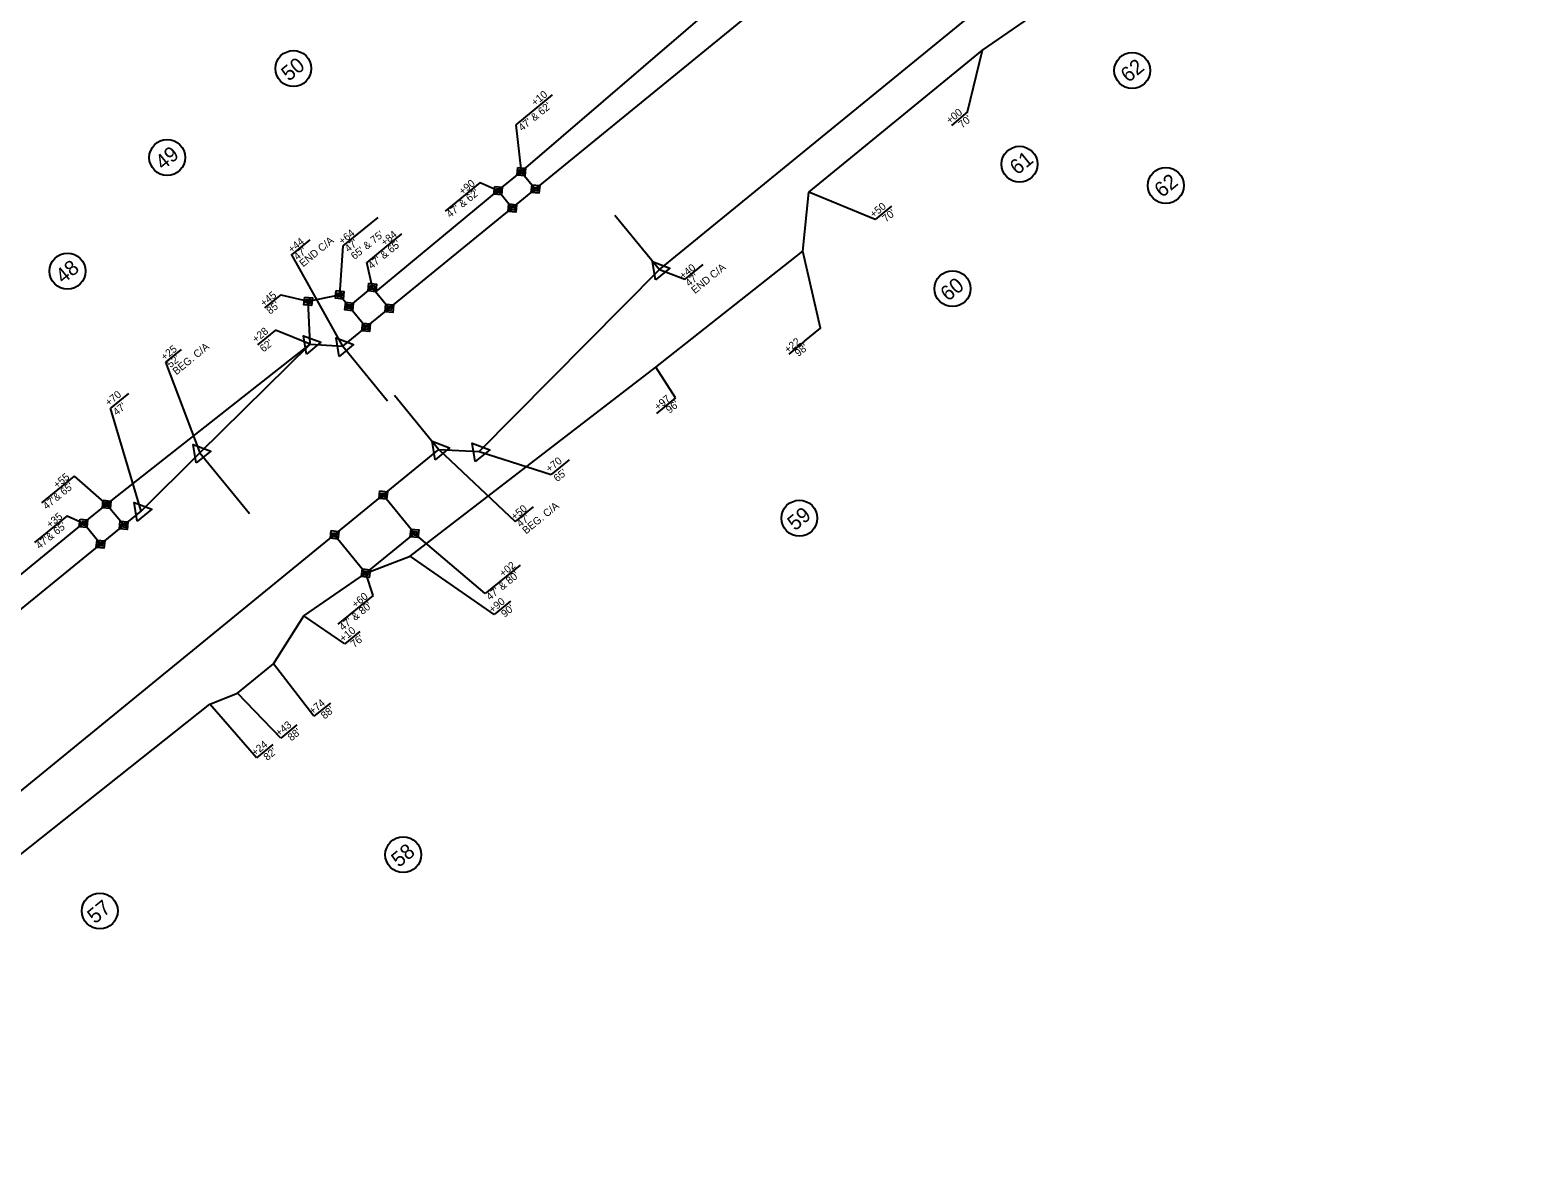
# Model space of a CAD drawing. Extents: x 2320946 to 2332748, y 597838 to 612698.
# Drawn here: x 2323947 to 2324954, y 599553 to 600307 of the extents above; entities that cross this region are included whole.
import ezdxf

# ---------------------------------------------------------------- set-up
doc = ezdxf.new("R2010")
doc.units = 0
for name, color, linetype in [('Prop Easement Construction', 7, 'Continuous'), ('Prop Easement Construction Station Offsets', 7, 'Continuous'), ('Prop Easement Permanent Drainage', 7, 'Continuous'), ('Prop Easement Permanent Drainage Station Offsets', 7, 'Continuous'), ('Prop Easement Permanent Drainage Utility', 7, 'Continuous'), ('Prop Easement Permanent Utility', 7, 'Continuous'), ('Prop Easement Permanent Utility Station Offsets', 7, 'Continuous'), ('Prop Parcel Number CELL', 7, 'Continuous'), ('Prop ROW CA Lines', 7, 'Continuous'), ('Prop ROW Marker CELL', 7, 'Continuous'), ('Prop ROW Permanent Easement CELL', 7, 'Continuous'), ('Prop ROW RW CA Lines', 7, 'Continuous'), ('Prop ROW RW Lines', 7, 'Continuous'), ('Prop ROW Station Offsets', 7, 'Continuous')]:
    doc.layers.add(name, color=color, linetype=linetype)

msp = doc.modelspace()

# ---------------------------------------------------------------- linework, layer by layer
at = {"layer": 'Prop Easement Construction'}
for p, q in [((2324275, 600212.5), (2324665.7, 600548.3)), ((2324583.1, 600293.7), (2324953.9, 600551.1)), ((2324467, 600198.8), (2324583.1, 600293.7)), ((2324177.8, 600132.4), (2324259.5, 600199.9)), ((2324463, 600159.4), (2324467, 600198.8)), ((2324364.9, 600081.9), (2324463, 600159.4)), ((2323998.1, 599990.3), (2324134, 600097.4)), ((2324200.7, 599955.7), (2324364.9, 600081.9)), ((2323839.3, 599860.7), (2323982.6, 599977.7)), ((2324171.2, 599944.4), (2324200.7, 599955.7)), ((2324129.9, 599915.9), (2324171.2, 599944.4)), ((2324109.6, 599883.8), (2324129.9, 599915.9)), ((2324085.6, 599864.2), (2324109.6, 599883.8)), ((2324067.1, 599856.9), (2324085.6, 599864.2)), ((2323904.1, 599727.7), (2324067.1, 599856.9))]:
    msp.add_line(p, q, dxfattribs=at)
at = {"layer": 'Prop Easement Construction Station Offsets'}
for p, q in [((2324573.1, 600252.4), (2324562.2, 600243.4)), ((2324522.3, 600189.6), (2324511.3, 600180.6)), ((2324464.2, 600099.3), (2324453.6, 600090.6)), ((2324378.1, 600061.5), (2324365.3, 600051)), ((2324267.7, 599925.7), (2324256.8, 599916.8)), ((2324167.2, 599905.5), (2324157.1, 599897.3)), ((2324147.5, 599857.7), (2324136.5, 599848.8)), ((2324125.2, 599843.1), (2324114.4, 599834.3)), ((2324109.1, 599830), (2324098.2, 599821.1))]:
    msp.add_line(p, q, dxfattribs=at)
for points in [[(2324573.1, 600252.4), (2324583.1, 600293.7)], [(2324511.3, 600180.6), (2324467, 600198.8)], [(2324464.2, 600099.3), (2324474.8, 600108), (2324463, 600159.4)], [(2324378.1, 600061.5), (2324364.9, 600081.9)], [(2324256.8, 599916.8), (2324200.7, 599955.7)], [(2324157.1, 599897.3), (2324129.9, 599915.9)], [(2324136.5, 599848.8), (2324109.6, 599883.8)], [(2324114.4, 599834.3), (2324085.6, 599864.2)], [(2324098.2, 599821.1), (2324067.1, 599856.9)]]:
    msp.add_lwpolyline(points, dxfattribs=at)
at = {"layer": 'Prop Easement Permanent Drainage'}
for p, q in [((2324259.5, 600199.9), (2324275, 600212.5)), ((2324275, 600212.5), (2324284.5, 600200.9)), ((2324259.5, 600199.9), (2324269, 600188.3)), ((2324160, 600122.5), (2324175.5, 600135.2)), ((2324175.5, 600135.2), (2324186.9, 600121.2)), ((2323982.6, 599977.7), (2323998.1, 599990.3)), ((2324009.5, 599976.4), (2323998.1, 599990.3))]:
    msp.add_line(p, q, dxfattribs=at)
at = {"layer": 'Prop Easement Permanent Drainage Station Offsets'}
for p, q in [((2324295.7, 600263.9), (2324271.3, 600243.9)), ((2324271.3, 600243.9), (2324275, 600212.5)), ((2324247.5, 600205.2), (2324224.2, 600186.2)), ((2324195.1, 600171), (2324171.8, 600151.9)), ((2323976.5, 600009.1), (2323954.7, 599991.3)), ((2323971.8, 599982.7), (2323950, 599964.9)), ((2323994, 599963.8), (2323982.6, 599977.7))]:
    msp.add_line(p, q, dxfattribs=at)
for points in [[(2324247.5, 600205.2), (2324259.5, 600199.9)], [(2324171.7, 600152), (2324175.5, 600135.2)], [(2323976.5, 600009.1), (2323998.1, 599990.3)], [(2323971.8, 599982.7), (2323982.6, 599977.7)]]:
    msp.add_lwpolyline(points, dxfattribs=at)
at = {"layer": 'Prop Easement Permanent Drainage Utility'}
msp.add_line((2324160, 600122.5), (2324171.4, 600108.6), dxfattribs=at)
at = {"layer": 'Prop Easement Permanent Utility'}
for p, q in [((2324132.7, 600126), (2324153.7, 600130.3)), ((2324134, 600097.4), (2324132.7, 600126)), ((2324153.7, 600130.3), (2324160, 600122.5)), ((2324203.7, 599971), (2324182.8, 599996.6)), ((2324150.3, 599970), (2324171.2, 599944.4)), ((2324171.2, 599944.4), (2324203.7, 599971))]:
    msp.add_line(p, q, dxfattribs=at)
at = {"layer": 'Prop Easement Permanent Utility Station Offsets'}
for p, q in [((2324179.3, 600182), (2324155.9, 600163)), ((2324114.5, 600130.4), (2324103.6, 600121.5)), ((2324251, 599930.9), (2324203.7, 599971)), ((2324274.2, 599949.8), (2324251, 599930.9)), ((2324176, 599929.4), (2324152.6, 599910.4))]:
    msp.add_line(p, q, dxfattribs=at)
for points in [[(2324155.9, 600163), (2324153.7, 600130.3)], [(2324114.5, 600130.4), (2324132.7, 600126)], [(2324176, 599929.4), (2324171.2, 599944.4)]]:
    msp.add_lwpolyline(points, dxfattribs=at)
at = {"layer": 'Prop Parcel Number CELL'}
for p, q in [((2324122.8, 600281.4), (2324122.8, 600281.4)), ((2324683, 600280.1), (2324683, 600280.1)), ((2324038.6, 600222), (2324038.6, 600222)), ((2324607.7, 600217.5), (2324607.7, 600217.5)), ((2324705.4, 600203.3), (2324705.4, 600203.3)), ((2323972, 600146.1), (2323972, 600146.1)), ((2324563, 600134.4), (2324563, 600134.4)), ((2324460.7, 599981.1), (2324460.7, 599981.1)), ((2324196.2, 599756.4), (2324196.2, 599756.4)), ((2323993.5, 599718.8), (2323993.5, 599718.8))]:
    msp.add_line(p, q, dxfattribs=at)
for centre in [(2324122.8, 600281.4), (2324683, 600280.1), (2324038.6, 600222), (2324607.7, 600217.5), (2324705.4, 600203.3), (2323972, 600146.1), (2324563, 600134.4), (2324460.7, 599981.1), (2324196.2, 599756.4), (2323993.5, 599718.8)]:
    msp.add_circle(centre, 12, dxfattribs=at)
at = {"layer": 'Prop ROW CA Lines'}
for p, q in [((2324337.5, 600183.5), (2324367.2, 600147.1)), ((2324155.9, 600095.9), (2324185.6, 600059.5)), ((2324190.3, 600063.3), (2324220, 600026.9)), ((2324060.4, 600024.7), (2324093.5, 599984.3))]:
    msp.add_line(p, q, dxfattribs=at)
at = {"layer": 'Prop ROW Marker CELL'}
for p, q in [((2324275, 600212.5), (2324275, 600212.5)), ((2324259.5, 600199.9), (2324259.5, 600199.9)), ((2324284.5, 600200.9), (2324284.5, 600200.9)), ((2324269, 600188.3), (2324269, 600188.3)), ((2324367.2, 600147.1), (2324367.2, 600147.1)), ((2324175.5, 600135.2), (2324175.5, 600135.2)), ((2324132.7, 600126), (2324132.7, 600126)), ((2324153.7, 600130.3), (2324153.7, 600130.3)), ((2324160, 600122.5), (2324160, 600122.5)), ((2324186.9, 600121.2), (2324186.9, 600121.2)), ((2324171.4, 600108.6), (2324171.4, 600108.6)), ((2324134, 600097.4), (2324134, 600097.4)), ((2324155.9, 600095.9), (2324155.9, 600095.9)), ((2324060.4, 600024.7), (2324060.4, 600024.7)), ((2324220, 600026.9), (2324220, 600026.9)), ((2324246.9, 600025.6), (2324246.9, 600025.6)), ((2324182.8, 599996.6), (2324182.8, 599996.6)), ((2323998.1, 599990.3), (2323998.1, 599990.3)), ((2324021.1, 599985.9), (2324021.1, 599985.9)), ((2323982.6, 599977.7), (2323982.6, 599977.7)), ((2324009.5, 599976.4), (2324009.5, 599976.4)), ((2323994, 599963.8), (2323994, 599963.8)), ((2324150.3, 599970), (2324150.3, 599970)), ((2324203.7, 599971), (2324203.7, 599971)), ((2324171.2, 599944.4), (2324171.2, 599944.4))]:
    msp.add_line(p, q, dxfattribs=at)
for points in [[(2324364.6, 600140.3), (2324362.6, 600152.6), (2324374.3, 600148.2)], [(2324131.5, 600090.7), (2324129.5, 600103), (2324141.2, 600098.6)], [(2324153.4, 600089.2), (2324151.4, 600101.5), (2324163, 600097.1)], [(2324217.4, 600020.2), (2324215.5, 600032.5), (2324227.1, 600028.1)], [(2324057.9, 600018), (2324055.9, 600030.3), (2324067.6, 600025.9)], [(2324244.3, 600018.9), (2324242.3, 600031.2), (2324254, 600026.8)], [(2324018.6, 599979.1), (2324016.6, 599991.5), (2324028.3, 599987.1)]]:
    msp.add_lwpolyline(points, close=True, dxfattribs=at)
at = {"layer": 'Prop ROW Permanent Easement CELL'}
for points in [[(2324272.7, 600215.3), (2324277.8, 600214.8), (2324277.3, 600209.7), (2324272.2, 600210.3)], [(2324273.9, 600213.9), (2324276.4, 600213.7), (2324276.2, 600211.1), (2324273.6, 600211.4)], [(2324257.3, 600202.7), (2324262.3, 600202.2), (2324261.8, 600197.1), (2324256.7, 600197.6)], [(2324282.2, 600203.7), (2324287.3, 600203.2), (2324286.8, 600198.1), (2324281.7, 600198.6)], [(2324258.4, 600201.3), (2324260.9, 600201), (2324260.7, 600198.5), (2324258.1, 600198.7)], [(2324283.4, 600202.3), (2324285.9, 600202), (2324285.6, 600199.5), (2324283.1, 600199.8)], [(2324266.7, 600191), (2324271.8, 600190.5), (2324271.3, 600185.5), (2324266.2, 600186)], [(2324267.9, 600189.7), (2324270.4, 600189.4), (2324270.2, 600186.9), (2324267.6, 600187.1)], [(2324151.4, 600133.1), (2324156.5, 600132.5), (2324156, 600127.5), (2324150.9, 600128)], [(2324173.2, 600138), (2324178.3, 600137.4), (2324177.8, 600132.4), (2324172.7, 600132.9)], [(2324174.4, 600136.6), (2324176.9, 600136.3), (2324176.7, 600133.8), (2324174.1, 600134)], [(2324130.4, 600128.8), (2324135.5, 600128.3), (2324134.9, 600123.2), (2324129.9, 600123.7)], [(2324131.5, 600127.4), (2324134.1, 600127.1), (2324133.8, 600124.6), (2324131.3, 600124.9)], [(2324152.6, 600131.7), (2324155.1, 600131.4), (2324154.8, 600128.9), (2324152.3, 600129.1)], [(2324157.8, 600125.3), (2324162.8, 600124.8), (2324162.3, 600119.7), (2324157.2, 600120.2)], [(2324158.9, 600123.9), (2324161.4, 600123.7), (2324161.2, 600121.1), (2324158.6, 600121.4)], [(2324184.6, 600124), (2324189.7, 600123.5), (2324189.2, 600118.4), (2324184.1, 600118.9)], [(2324185.8, 600122.6), (2324188.3, 600122.4), (2324188, 600119.8), (2324185.5, 600120.1)], [(2324169.1, 600111.4), (2324174.2, 600110.9), (2324173.7, 600105.8), (2324168.6, 600106.3)], [(2324170.3, 600110), (2324172.8, 600109.7), (2324172.6, 600107.2), (2324170, 600107.4)], [(2323995.9, 599993.1), (2324000.9, 599992.6), (2324000.4, 599987.6), (2323995.3, 599988.1)], [(2323997, 599991.7), (2323999.5, 599991.5), (2323999.3, 599989), (2323996.7, 599989.2)], [(2324180.6, 599999.3), (2324185.6, 599998.8), (2324185.1, 599993.8), (2324180, 599994.3)], [(2324181.7, 599997.9), (2324184.2, 599997.7), (2324184, 599995.2), (2324181.4, 599995.4)], [(2323980.4, 599980.5), (2323985.4, 599980), (2323984.9, 599974.9), (2323979.8, 599975.4)], [(2323981.5, 599979.1), (2323984, 599978.8), (2323983.8, 599976.3), (2323981.2, 599976.6)], [(2324007.2, 599979.2), (2324012.3, 599978.7), (2324011.8, 599973.6), (2324006.7, 599974.1)], [(2324008.4, 599977.8), (2324010.9, 599977.5), (2324010.7, 599975), (2324008.1, 599975.3)], [(2324148, 599972.8), (2324153.1, 599972.3), (2324152.6, 599967.2), (2324147.5, 599967.7)], [(2324149.2, 599971.4), (2324151.7, 599971.1), (2324151.4, 599968.6), (2324148.9, 599968.9)], [(2324201.4, 599973.8), (2324206.5, 599973.3), (2324206, 599968.2), (2324200.9, 599968.7)], [(2324202.6, 599972.4), (2324205.1, 599972.1), (2324204.8, 599969.6), (2324202.3, 599969.9)], [(2323991.7, 599966.5), (2323996.8, 599966), (2323996.3, 599961), (2323991.2, 599961.5)], [(2323992.9, 599965.2), (2323995.4, 599964.9), (2323995.2, 599962.4), (2323992.6, 599962.6)], [(2324168.9, 599947.2), (2324174, 599946.7), (2324173.4, 599941.6), (2324168.4, 599942.2)], [(2324170, 599945.8), (2324172.6, 599945.6), (2324172.3, 599943), (2324169.8, 599943.3)]]:
    msp.add_lwpolyline(points, close=True, dxfattribs=at)
at = {"layer": 'Prop ROW RW CA Lines'}
for p, q in [((2324246.9, 600025.6), (2324367.2, 600147.1)), ((2324060.4, 600024.7), (2324134, 600097.4)), ((2324134, 600097.4), (2324155.9, 600095.9)), ((2324220, 600026.9), (2324246.9, 600025.6))]:
    msp.add_line(p, q, dxfattribs=at)
at = {"layer": 'Prop ROW RW Lines'}
for p, q in [((2324367.2, 600147.1), (2324917.2, 600596.1)), ((2324155.9, 600095.9), (2324687.3, 600529.8)), ((2323639, 599552.6), (2324220, 600026.9)), ((2324021.1, 599985.9), (2324060.4, 600024.7)), ((2323734.5, 599751.9), (2324021.1, 599985.9))]:
    msp.add_line(p, q, dxfattribs=at)
at = {"layer": 'Prop ROW Station Offsets'}
for p, q in [((2324133.8, 600167.1), (2324121.8, 600157.3)), ((2324155.9, 600095.9), (2324121.5, 600157.5)), ((2324367.2, 600147.1), (2324384.2, 600140.7)), ((2324396.2, 600150.5), (2324384.2, 600140.7)), ((2324110.9, 600106.7), (2324098.8, 600096.8)), ((2324134, 600097.4), (2324110.9, 600106.7)), ((2324047.9, 600093.7), (2324037.5, 600085.3)), ((2324012.6, 600064.3), (2324000.6, 600054.5)), ((2324021.1, 599985.9), (2324000.6, 600054.5)), ((2324220, 600026.9), (2324271, 599979)), ((2324246.9, 600025.6), (2324294.9, 600010.2)), ((2324306.9, 600020), (2324294.9, 600010.2)), ((2324283, 599988.8), (2324271, 599979))]:
    msp.add_line(p, q, dxfattribs=at)
msp.add_lwpolyline([(2324037.5, 600085.3), (2324060.4, 600024.7)], dxfattribs=at)

# ---------------------------------------------------------------- texts
at = {"layer": 'Prop Easement Construction Station Offsets'}
for s, p in [('+00', (2324561.2, 600244.2)), ("70'", (2324569.4, 600241.3)), ('+50', (2324510.3, 600181.4)), ("70'", (2324518.6, 600178.5)), ('+22', (2324453.1, 600091)), ("98'", (2324460.1, 600088.7)), ('+97', (2324366.3, 600052.8)), ("96'", (2324374.1, 600050.8)), ('+90', (2324255.8, 599917.5)), ("90'", (2324264, 599914.6)), ('+10', (2324156.1, 599898.1)), ("76'", (2324163.5, 599894.4)), ('+74', (2324135.7, 599849.7)), ("88'", (2324143.7, 599846.6)), ('+43', (2324113.3, 599835.1)), ("88'", (2324121.5, 599832)), ('+24', (2324097.3, 599822)), ("82'", (2324105.4, 599818.9))]:
    msp.add_text(s, height=5, rotation=39.228, dxfattribs=at).set_placement(p)
at = {"layer": 'Prop Easement Permanent Drainage Station Offsets'}
for s, p in [('+10', (2324284.2, 600256.1)), ("47' & 62'", (2324275.6, 600239.3)), ('+90', (2324235.8, 600196.7)), ("47' & 62'", (2324227.5, 600181.5)), ('+84', (2324183.7, 600162.6)), ("47' & 65'", (2324175.1, 600147.2)), ('+55', (2323965, 600000.7)), ("47'& 65'", (2323958, 599986.6)), ('+35', (2323960.3, 599974.3)), ("47'& 65'", (2323953.3, 599960.2))]:
    msp.add_text(s, height=5, rotation=39.228, dxfattribs=at).set_placement(p)
at = {"layer": 'Prop Easement Permanent Utility Station Offsets'}
for s, p in [('+64', (2324155.5, 600163.5)), ("65' & 75'", (2324163.7, 600153.5)), ("47' ", (2324159.6, 600158.5)), ('+45', (2324103.2, 600122.1)), ("85'", (2324107.3, 600117)), ('+02', (2324262.9, 599941.6)), ("47' & 80'", (2324254.1, 599926)), ('+60', (2324164.3, 599920.9)), ("47' & 80'", (2324155.9, 599905.7))]:
    msp.add_text(s, height=5, rotation=39.228, dxfattribs=at).set_placement(p)
at = {"layer": 'Prop Parcel Number CELL'}
for s, p in [('50', (2324119.8, 600272.5)), ('62', (2324680.4, 600271.6)), ('49', (2324035.7, 600213.2)), ('61', (2324606.3, 600209.9)), ('62', (2324702.9, 600194.8)), ('48', (2323969.1, 600137.3)), ('60', (2324560, 600125.5)), ('59', (2324457.8, 599972.3)), ('58', (2324193.3, 599747.5)), ('57', (2323990.3, 599709.8))]:
    msp.add_text(s, height=10, rotation=39.228, dxfattribs=at).set_placement(p)
at = {"layer": 'Prop ROW Station Offsets'}
for s, p in [('+44', (2324121.7, 600157.9)), ("47'", (2324125.5, 600153.2)), ('END C/A', (2324129.3, 600148.6)), ('+40', (2324383.1, 600140.4)), ("47'", (2324387.1, 600135.5)), ('END C/A', (2324391, 600130.7)), ('+28', (2324097.8, 600098)), ('+25', (2324036.8, 600086.1)), ('BEG. C/A', (2324044.7, 600076.5)), ("62'", (2324102.9, 600091.7)), ("52'", (2324040.8, 600081.3)), ('+70', (2323999.6, 600055.7)), ("47'", (2324004.8, 600049.4)), ('+70', (2324293.9, 600011.4)), ("65'", (2324299.1, 600005.1)), ('BEG. C/A', (2324278.2, 599970.2)), ('+50', (2324270.6, 599979.5)), ("47'", (2324274.4, 599974.8))]:
    msp.add_text(s, height=5, rotation=39.228, dxfattribs=at).set_placement(p)

doc.saveas('drawing.dxf')
